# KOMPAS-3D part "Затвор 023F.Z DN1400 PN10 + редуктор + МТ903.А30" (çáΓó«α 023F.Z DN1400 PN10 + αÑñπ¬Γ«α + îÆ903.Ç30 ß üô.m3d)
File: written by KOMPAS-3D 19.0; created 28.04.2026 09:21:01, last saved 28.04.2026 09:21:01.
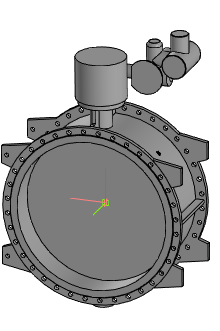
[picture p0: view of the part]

Document properties: Автор: Энергия; Полное имя файла: ..\Затвор 023F.Z DN1400 PN10 + редуктор + МТ903.А30.a3d

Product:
- Part/product: Затвор 023F.Z DN1400 PN10 + редуктор + МТ903.А30
    Масса: 3605.29

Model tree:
1. Операция без истории:1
